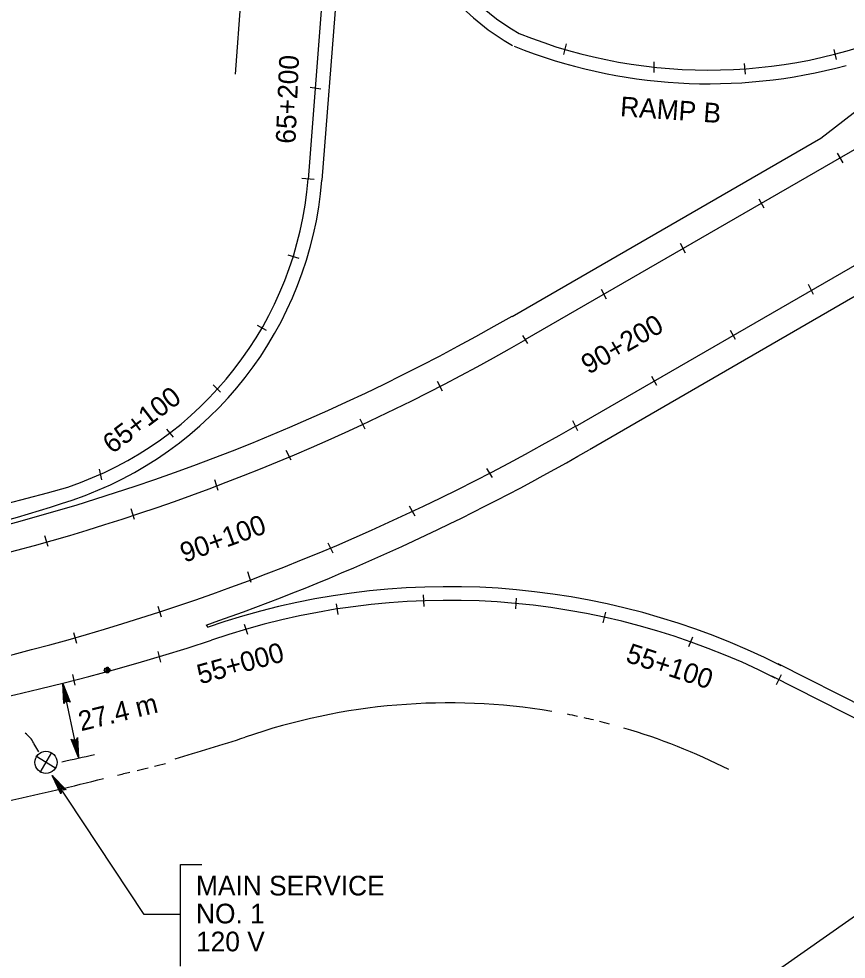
# Model space of a CAD drawing. Extents: x 36 to 2622, y -5330 to 219.
# Drawn here: x 1877.5 to 2003.5, y -4537.5 to -4394.4 of the extents above; entities that cross this region are included whole.
import ezdxf

# ---------------------------------------------------------------- set-up
doc = ezdxf.new("R2010")
doc.units = 0
doc.layers.add('2', color=7, linetype='Continuous')
doc.layers.add('3', color=7, linetype='Continuous')

# ---------------------------------------------------------------- blocks, each defined once
blk = doc.blocks.new('RARROW')
at = {"layer": '3'}
blk.add_lwpolyline([(-2.2695, 0.285), (-2.184875, 0.12075), (0, 0), (-2.2695, 0.285), (-2.38575, 0.384625), (0, 0), (-2.183125, -0.108), (-2.262875, -0.2705), (0, 0), (-2.38575, -0.379125), (-2.262875, -0.2705)], dxfattribs=at)

msp = doc.modelspace()

# ---------------------------------------------------------------- linework, layer by layer
at = {"layer": '2'}
for p, q in [((2538.01, -4157.41), (1748.46, -4710.54)), ((1954.61, -4443.2), (2241.98, -4277.33)), ((1962.23, -4456.45), (2237.61, -4297.45)), ((1921.61, -4418.83), (1927.98, -4336.2)), ((1930.11, -4336.33), (1923.61, -4418.95)), ((1910.48, -4402.83), (1912.36, -4377.45)), ((1960.48, -4399.83), (1960.86, -4398.2)), ((1999.61, -4412.58), (2019.61, -4396.95)), ((2001.98, -4400.58), (2001.61, -4399.08)), ((1964.36, -4459.95), (2068.36, -4399.83)), ((1974.23, -4402.58), (1974.23, -4400.95)), ((1988.11, -4402.83), (1987.98, -4401.2)), ((1923.48, -4405.08), (1921.86, -4404.83)), ((1952.61, -4439.7), (1999.61, -4412.58)), ((2002.98, -4416.33), (2002.11, -4414.83)), ((1922.48, -4418.83), (1920.61, -4418.7)), ((1990.98, -4423.2), (1990.23, -4421.83)), ((1978.98, -4430.08), (1978.23, -4428.58)), ((1918.48, -4430.33), (1920.11, -4430.83)), ((1998.48, -4436.33), (1997.73, -4434.83)), ((1966.98, -4437.08), (1966.23, -4435.58)), ((1915.23, -4441.83), (1913.86, -4441.08)), ((1954.98, -4443.83), (1954.23, -4442.58)), ((1986.61, -4443.2), (1985.86, -4441.83)), ((1941.98, -4451.08), (1941.23, -4449.58)), ((1974.61, -4450.2), (1973.86, -4448.83)), ((1907.11, -4450.08), (1908.23, -4451.2)), ((1930.23, -4456.83), (1929.48, -4455.33)), ((1899.98, -4456.83), (1900.98, -4458.08)), ((1962.61, -4457.08), (1961.86, -4455.58)), ((1918.98, -4461.58), (1918.23, -4460.08)), ((1889.73, -4462.95), (1890.11, -4464.58)), ((1949.61, -4464.2), (1948.73, -4462.83)), ((1907.86, -4466.2), (1907.36, -4464.58)), ((1895.11, -4470.58), (1894.61, -4468.95)), ((1937.86, -4470.08), (1936.98, -4468.58)), ((1881.98, -4474.7), (1881.48, -4473.08)), ((1925.36, -4475.7), (1924.61, -4474.2)), ((1912.86, -4480.2), (1912.36, -4478.58)), ((1939.23, -4483.83), (1939.11, -4482.08)), ((1953.23, -4482.58), (1953.11, -4484.2)), ((1899.23, -4485.45), (1898.73, -4483.83)), ((1926.11, -4485.08), (1925.86, -4483.45)), ((1966.48, -4486.33), (1966.86, -4484.7)), ((1906.23, -4486.95), (1906.11, -4486.7)), ((1912.36, -4488.08), (1911.86, -4486.58)), ((1886.36, -4489.45), (1885.86, -4487.83)), ((1979.48, -4489.95), (1980.11, -4488.45)), ((1899.11, -4492.33), (1898.73, -4490.7)), ((2033.61, -4513.08), (1993.11, -4492.58)), ((1886.11, -4495.83), (1885.73, -4494.2)), ((2032.61, -4514.95), (1992.11, -4494.45)), ((1992.86, -4495.7), (1993.61, -4494.2)), ((1886.61, -4506.83), (1884.23, -4495.58)), ((1879.73, -4504.7), (1880.48, -4505.95)), ((1880.11, -4506.58), (1882.98, -4508.33)), ((1882.48, -4506.08), (1880.73, -4509.08)), ((1896.61, -4530.7), (1882.61, -4509.58)), ((1902.11, -4538.58), (1902.11, -4523.08)), ((1902.11, -4523.08), (1905.36, -4523.08)), ((1902.11, -4530.7), (1896.61, -4530.7))]:
    msp.add_line(p, q, dxfattribs=at)
msp.add_lwpolyline([(1890.98, -4493.58), (1890.98, -4493.58), (1890.98, -4493.58), (1890.98, -4493.58), (1891.11, -4493.58), (1890.98, -4493.58), (1890.98, -4493.7), (1890.86, -4493.7), (1890.86, -4493.58), (1890.86, -4493.33), (1890.98, -4493.33), (1891.11, -4493.33), (1891.11, -4493.58), (1891.11, -4493.7), (1890.98, -4493.7), (1890.86, -4493.7), (1890.86, -4493.58), (1890.86, -4493.33), (1890.86, -4493.33), (1890.98, -4493.2), (1891.11, -4493.33), (1891.23, -4493.58), (1891.23, -4493.7), (1891.11, -4493.83), (1890.98, -4493.83), (1890.86, -4493.83), (1890.61, -4493.7), (1890.61, -4493.58), (1890.61, -4493.33), (1890.86, -4493.2), (1890.98, -4493.2), (1891.11, -4493.2), (1891.23, -4493.33), (1891.23, -4493.58), (1891.23, -4493.7), (1891.23, -4493.83), (1891.11, -4493.83), (1890.98, -4493.95), (1890.86, -4493.95), (1890.61, -4493.83), (1890.61, -4493.7), (1890.48, -4493.58), (1890.48, -4493.58), (1890.61, -4493.33), (1890.61, -4493.2), (1890.86, -4493.2), (1890.98, -4493.08), (1891.11, -4493.08), (1891.11, -4493.2), (1891.23, -4493.2), (1891.23, -4493.33), (1891.36, -4493.33), (1891.36, -4493.58), (1891.36, -4493.7), (1891.23, -4493.83), (1891.23, -4493.83), (1891.11, -4493.95), (1890.98, -4493.95), (1890.86, -4493.95), (1890.86, -4493.95), (1890.61, -4493.83)], dxfattribs=at)
msp.add_circle((1881.64, -4507.56), 1.7, dxfattribs=at)
for centre, radius, start, end in [((1970.81, -4366.68), 36.6, 97.1666, 240.2478), ((1970.81, -4366.68), 34.52, 97.1666, 240.2478), ((1982.51, -4324.65), 77.55, 248.1807, 294.519), ((1982.51, -4324.65), 79.63, 248.1807, 285.2322), ((1867.78, -4414.53), 53.94, 288.593, 355.4986), ((1867.78, -4414.53), 56.03, 288.593, 355.4986), ((1794.42, -4165.65), 316.36, 281.7273, 300.0002), ((1794.42, -4165.65), 320.5, 267.9323, 300.0002), ((1794.42, -4165.65), 335.7, 268.3537, 300.0002), ((1794.42, -4165.65), 339.86, 289.1726, 300.0002), ((1781.15, -4099.53), 380.57, 270.3722, 285.832), ((1821.28, -4276.29), 201.88, 280.6512, 288.5929), ((1942.96, -4593.2), 112.38, 63.231, 109.1121), ((1942.96, -4593.2), 110.3, 63.231, 109.1117), ((1801.48, -4165.86), 339.86, 267.0898, 288.0608), ((1942.96, -4593.2), 94.69, 80.4637, 109.1117), ((1942.96, -4593.2), 94.69, 78.07, 79.0084), ((1942.96, -4593.2), 94.69, 76.5427, 77.426), ((1942.96, -4593.2), 94.69, 75.0158, 75.9661), ((1942.96, -4593.2), 94.69, 63.231, 73.6434), ((1876.1, -4506.56), 4.16, 27.5244, 55.3399), ((1802.72, -4168.74), 352.35, 286.2455, 288.0608), ((1810.62, -4162.85), 352.35, 282.0309, 282.8538), ((1813.53, -4166.12), 352.35, 283.4566, 283.733), ((1813.53, -4166.12), 352.35, 283.8944, 284.1806), ((1813.53, -4166.12), 352.35, 282.9562, 283.2733), ((1802.72, -4168.74), 352.35, 282.0309, 284.4105)]:
    msp.add_arc(centre, radius, start, end, dxfattribs=at)

# ---------------------------------------------------------------- block references
at = {"layer": '2', "yscale": 1.3092961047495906}
for p, xscale, rotation in [((1884.23, -4495.58), 1.2574347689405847, 101.84152231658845), ((1886.61, -4506.83), 1.2574347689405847, -77.57392872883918), ((1882.61, -4509.58), 1.257434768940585, 124.92623775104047)]:
    msp.add_blockref('RARROW', p, dxfattribs=dict(at, xscale=xscale, rotation=rotation))

# ---------------------------------------------------------------- texts
at = {"layer": '2'}
for s, height, rotation, p in [('65+200', 3, 87.6081, (1919.61, -4413.45)), ('RAMP B', 2.996, 356.0128, (1968.98, -4409.2)), ('90+200', 3, 30, (1964.23, -4448.58)), ('65+100', 3, 37.2248, (1891.73, -4460.7)), ('90+100', 3, 20, (1902.73, -4477.2)), ('55+000', 3, 15.3615, (1905.11, -4495.7)), ('55+100', 3, 341.5611, (1969.73, -4492.2)), ('27.4 m', 3, 13.7638, (1886.98, -4502.83))]:
    msp.add_text(s, height=height, rotation=rotation, dxfattribs=at).set_placement(p)
for s, height, p in [('MAIN SERVICE', 2.9955, (1904.48, -4527.82)), ('NO. 1', 2.996, (1904.48, -4532.07)), ('120 V ', 2.996, (1904.48, -4536.32))]:
    msp.add_text(s, height=height, dxfattribs=at).set_placement(p)

doc.saveas('drawing.dxf')
